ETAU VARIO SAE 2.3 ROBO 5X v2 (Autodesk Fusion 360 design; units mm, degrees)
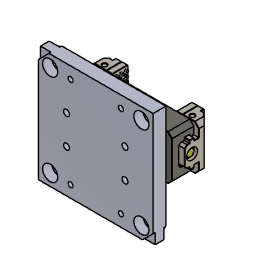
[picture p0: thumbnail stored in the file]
parameter "Ouverture" = 110
base_feature "Base Feature1" OffsetX 0 OffsetY 0 OffsetZ 0 AngleZ 0
base_feature "Base Feature1"
base_feature "Base Feature1"
base_feature "Base Feature1"
position "Position1"
joint_origin "JointOrigin1" OffsetX 0 OffsetY 0 OffsetZ 0 AngleZ 0
as_built_joint "As-built1"
as_built_joint "As-built2"
work_axis "WorkAxis1"
work_point "WorkPoint1"
joint_origin "JointOrigin1" OffsetX 0 OffsetY 0 OffsetZ 0 AngleZ 0
joint "Assemble3" alignAngle 0 alignOffsetX 0 alignOffsetY 0 alignOffsetZ 55 (= "Ouverture / 2")
joint "Assemble4" alignAngle 180 alignOffsetX 0 alignOffsetY 0 alignOffsetZ 55 (= "Ouverture / 2")
ground "Ground1"
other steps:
create_component "CreateComponent1"
create_component "CreateComponent2"
create_component "CreateComponent3"
create_component "CreateComponent4"
joint_origin "JointOrigin4" OffsetX 0 OffsetY 0 OffsetZ 0 AngleZ 0
joint_origin "JointOrigin5" OffsetX 0 OffsetY 0 OffsetZ 0 AngleZ 0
